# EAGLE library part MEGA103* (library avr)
MICROCONTROLLER Low-voltage (L) 128 Kbytes FLASH 4 Kbytes SRAM 2 Kbytes EEPROM UART RTC 8-channel 10 bit ADC
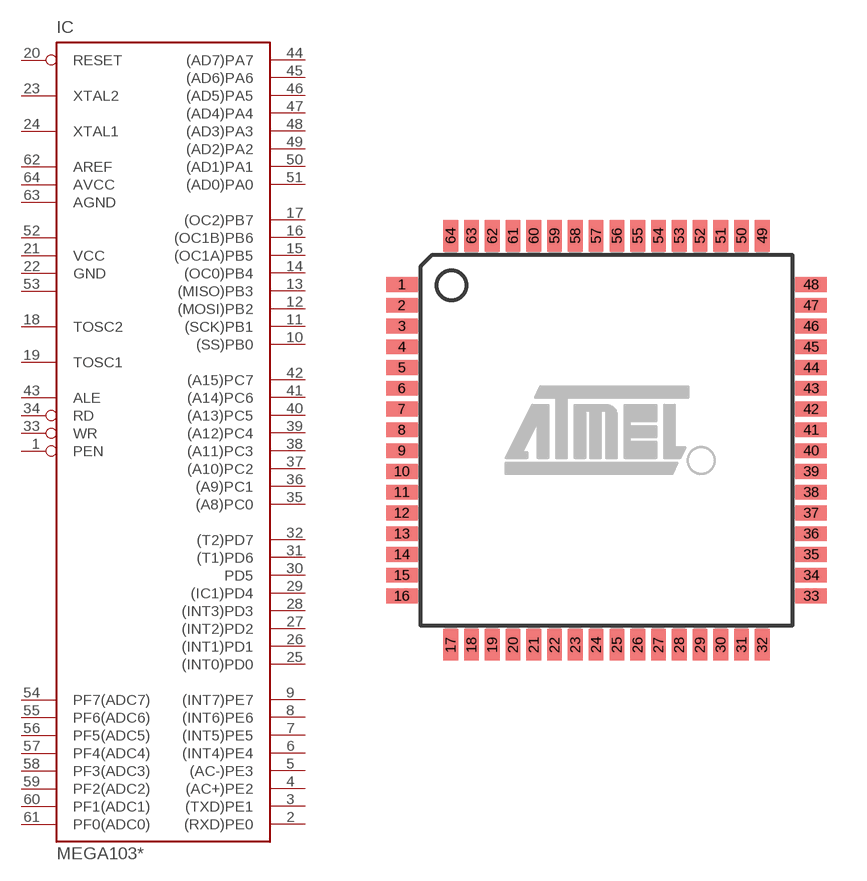
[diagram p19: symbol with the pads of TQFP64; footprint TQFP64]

Designator prefix IC

## MEGA103-8A, MEGA103L-4A  [TQFP64]
1  PEN  in
2  (RXD)PE0
3  (TXD)PE1
4  (AC+)PE2
5  (AC-)PE3
6  (INT4)PE4
7  (INT5)PE5
8  (INT6)PE6
9  (INT7)PE7
10  (SS)PB0
11  (SCK)PB1
12  (MOSI)PB2
13  (MISO)PB3
14  (OC0)PB4
15  (OC1A)PB5
16  (OC1B)PB6
17  (OC2)PB7
18  TOSC2
19  TOSC1
20  RESET  in
21  VCC  pwr
22  GND  pwr
23  XTAL2
24  XTAL1
25  (INT0)PD0
26  (INT1)PD1
27  (INT2)PD2
28  (INT3)PD3
29  (IC1)PD4
30  PD5
31  (T1)PD6
32  (T2)PD7
33  WR
34  RD
35  (A8)PC0  out
36  (A9)PC1  out
37  (A10)PC2  out
38  (A11)PC3  out
39  (A12)PC4  out
40  (A13)PC5  out
41  (A14)PC6  out
42  (A15)PC7  out
43  ALE
44  (AD7)PA7
45  (AD6)PA6
46  (AD5)PA5
47  (AD4)PA4
48  (AD3)PA3
49  (AD2)PA2
50  (AD1)PA1
51  (AD0)PA0
52  VCC1  pwr
53  GND1  pwr
54  PF7(ADC7)  in
55  PF6(ADC6)  in
56  PF5(ADC5)  in
57  PF4(ADC4)  in
58  PF3(ADC3)  in
59  PF2(ADC2)  in
60  PF1(ADC1)  in
61  PF0(ADC0)  in
62  AREF
63  AGND
64  AVCC

## Footprint TQFP64 (pad centres in mm)
Thin Plasic Quad Flat Package
smd 1.194 x 0.559: 1 -7.76,5.905; 2 -7.76,5.118; 3 -7.76,4.331; 4 -7.76,3.543; 5 -7.76,2.756; 6 -7.76,1.968; 7 -7.76,1.181; 8 -7.76,0.394; 9 -7.76,-0.394; 10 -7.76,-1.181; 11 -7.76,-1.968; 12 -7.76,-2.756; 13 -7.76,-3.543; 14 -7.76,-4.331; 15 -7.76,-5.118; 16 -7.76,-5.905; 33 7.76,-5.905; 34 7.76,-5.118; 35 7.76,-4.331; 36 7.76,-3.543; 37 7.76,-2.756; 38 7.76,-1.968; 39 7.76,-1.181; 40 7.76,-0.394; 41 7.76,0.394; 42 7.76,1.181; 43 7.76,1.968; 44 7.76,2.756; 45 7.76,3.543; 46 7.76,4.331; 47 7.76,5.118; 48 7.76,5.905
smd 0.559 x 1.194: 17 -5.905,-7.76; 18 -5.118,-7.76; 19 -4.331,-7.76; 20 -3.543,-7.76; 21 -2.756,-7.76; 22 -1.968,-7.76; 23 -1.181,-7.76; 24 -0.394,-7.76; 25 0.394,-7.76; 26 1.181,-7.76; 27 1.968,-7.76; 28 2.756,-7.76; 29 3.543,-7.76; 30 4.331,-7.76; 31 5.118,-7.76; 32 5.905,-7.76; 49 5.905,7.76; 50 5.118,7.76; 51 4.331,7.76; 52 3.543,7.76; 53 2.756,7.76; 54 1.968,7.76; 55 1.181,7.76; 56 0.394,7.76; 57 -0.394,7.76; 58 -1.181,7.76; 59 -1.968,7.76; 60 -2.756,7.76; 61 -3.543,7.76; 62 -4.331,7.76; 63 -5.118,7.76; 64 -5.905,7.76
